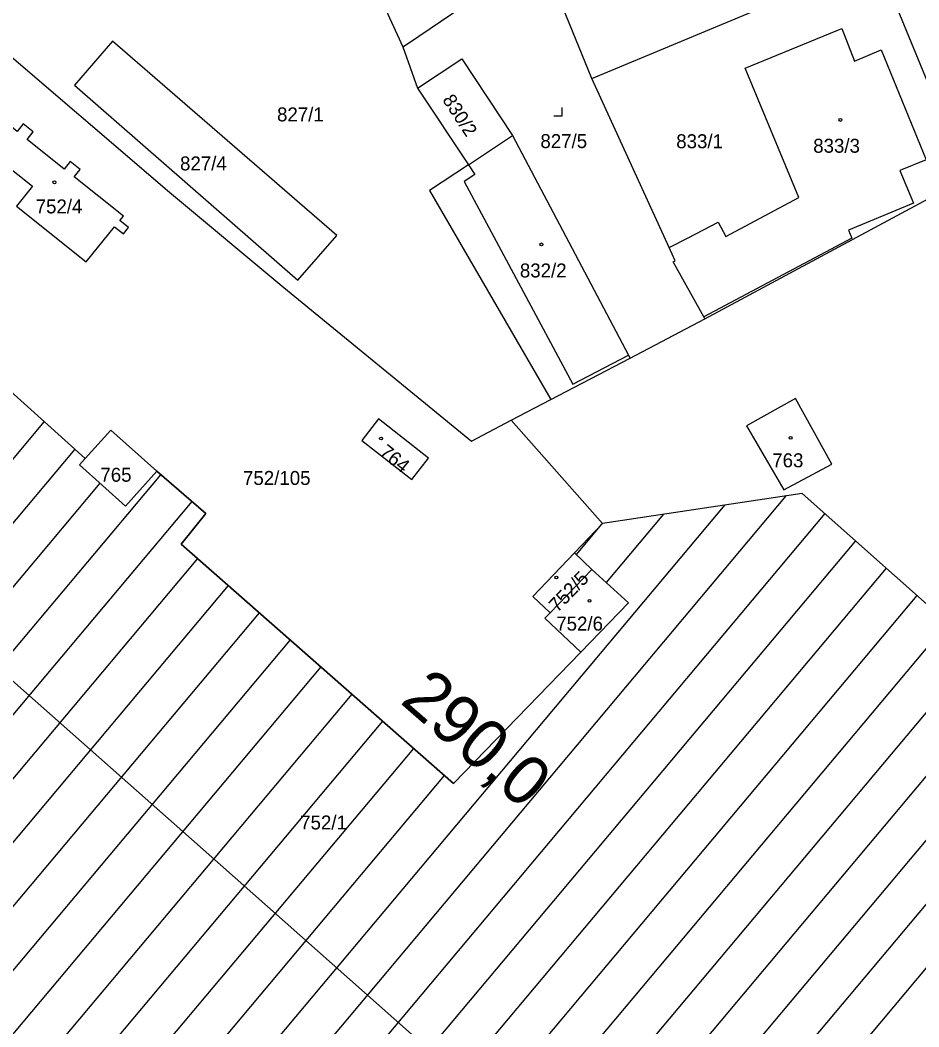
# Model space of a CAD drawing. Extents: x -496682 to -495776, y -1088797 to -1088018.
# Drawn here: x -496303.3 to -496193.9, y -1088379.3 to -1088256.7 of the extents above; entities that cross this region are included whole.
import ezdxf

# ---------------------------------------------------------------- set-up
doc = ezdxf.new("R2010")
doc.units = 0
for name, color, linetype in [('_PS01_CCTV', 7, 'Continuous'), ('Hranice parcel', 7, 'Continuous'), ('Parcelní čísla', 7, 'Continuous'), ('Vnitřní kresba', 7, 'Continuous'), ('Vrstva 20', 7, 'Continuous'), ('Vrstva 54', 7, 'Continuous'), ('Vrstva 7', 7, 'Continuous'), ('Značky budov', 7, 'Continuous'), ('Značky kultur', 7, 'Continuous')]:
    doc.layers.add(name, color=color, linetype=linetype)

msp = doc.modelspace()

# ---------------------------------------------------------------- linework, layer by layer
at = {"layer": '_PS01_CCTV'}
for p, q in [((-496278.91, -1088359.52), (-496318.03, -1088324.96)), ((-496244.22, -1088390.26), (-496278.91, -1088359.52))]:
    msp.add_line(p, q, dxfattribs=at)
at = {"layer": 'Hranice parcel'}
for p, q in [((-496188.02, -1088275.91), (-496199.66, -1088247.57)), ((-496261.03, -1088250.54), (-496256.69, -1088259.96)), ((-496256.69, -1088259.96), (-496254.9, -1088264.97)), ((-496224.27, -1088284.4), (-496233.69, -1088263.8)), ((-496254.9, -1088264.97), (-496248.71, -1088274.32)), ((-496248.71, -1088274.32), (-496243.33, -1088270.76)), ((-496219.91, -1088293.08), (-496188.02, -1088275.91)), ((-496229.03, -1088297.84), (-496219.91, -1088293.08)), ((-496219.91, -1088293.08), (-496220.05, -1088292.84)), ((-496238.7, -1088302.89), (-496229.03, -1088297.84)), ((-496243.5, -1088305.4), (-496238.7, -1088302.89)), ((-496232.37, -1088317.97), (-496243.5, -1088305.4)), ((-496232.37, -1088317.97), (-496235.81, -1088321.54)), ((-496235.81, -1088321.54), (-496233.69, -1088323.57)), ((-496238.78, -1088328.84), (-496233.69, -1088323.57))]:
    msp.add_line(p, q, dxfattribs=at)
for points in [[(-496233.69, -1088263.8), (-496239.59, -1088249.36), (-496229.63, -1088245.28)], [(-496256.69, -1088259.96), (-496256.02, -1088259.51), (-496241.58, -1088249.7)], [(-496233.69, -1088263.8), (-496212.34, -1088254.94), (-496213.15, -1088252.87)], [(-496224.27, -1088284.4), (-496221.97, -1088283.2), (-496218.31, -1088281.3), (-496217.38, -1088283.04), (-496208.49, -1088278.31), (-496215.03, -1088262.55), (-496203.26, -1088257.73), (-496201.7, -1088261.7), (-496198.45, -1088260.34), (-496192.96, -1088273.71), (-496196.19, -1088275), (-496194.54, -1088278.98), (-496202.44, -1088282.27), (-496202.01, -1088283.23), (-496220.05, -1088292.84)], [(-496306.94, -1088258.98), (-496285.12, -1088277.63), (-496271.2, -1088289.24), (-496248.36, -1088307.94), (-496243.5, -1088305.4)], [(-496292.05, -1088259.28), (-496296.7, -1088264.61), (-496269.47, -1088288.37), (-496264.72, -1088282.93), (-496292.05, -1088259.28)], [(-496254.9, -1088264.97), (-496249.52, -1088261.41), (-496243.33, -1088270.76)], [(-496295.37, -1088310.06), (-496327.63, -1088281.05), (-496324.32, -1088278.18), (-496332.44, -1088271.21), (-496325.94, -1088264.24)], [(-496303.66, -1088270.27), (-496306.43, -1088268.03), (-496305.87, -1088267.33), (-496307.07, -1088266.38), (-496307.63, -1088267.08), (-496310.05, -1088265.15), (-496312.56, -1088268.38), (-496301.78, -1088276.93), (-496303.73, -1088279.34), (-496295.25, -1088286.14), (-496291.81, -1088281.87), (-496290.73, -1088282.73), (-496290.1, -1088281.93), (-496291.18, -1088281.08), (-496290.73, -1088280.58), (-496296.73, -1088275.79), (-496296, -1088274.87), (-496297.2, -1088273.92), (-496297.93, -1088274.83), (-496302.46, -1088271.23), (-496301.72, -1088270.3), (-496302.92, -1088269.34), (-496303.66, -1088270.27)], [(-496243.33, -1088270.76), (-496229.21, -1088297.49), (-496229.03, -1088297.84)], [(-496248.71, -1088274.32), (-496253.45, -1088277.46), (-496238.7, -1088302.89)], [(-496220.05, -1088292.84), (-496223.77, -1088286.13), (-496223.53, -1088286), (-496224.27, -1088284.4)], [(-496214.86, -1088306.08), (-496210.29, -1088313.89), (-496204.48, -1088310.74), (-496208.88, -1088302.76), (-496214.86, -1088306.08)], [(-496255.61, -1088312.64), (-496253.57, -1088310.04), (-496259.65, -1088305.26), (-496261.69, -1088307.86), (-496255.61, -1088312.64)], [(-496286.66, -1088311.63), (-496292.26, -1088306.61), (-496295.37, -1088310.06)], [(-496286.66, -1088311.63), (-496290.49, -1088315.87), (-496296.07, -1088310.84), (-496295.37, -1088310.06)], [(-496235.04, -1088333.66), (-496250.52, -1088349.65), (-496283.68, -1088320.49), (-496280.68, -1088316.78), (-496286.66, -1088311.63)], [(-496085.86, -1088384.22), (-496089.4, -1088386.33), (-496106.83, -1088404.69), (-496113.8, -1088398.15), (-496126.07, -1088387.1), (-496145.34, -1088370.03), (-496208.08, -1088314.32), (-496232.37, -1088317.97)], [(-496235.81, -1088321.54), (-496240.87, -1088326.86), (-496238.78, -1088328.84)], [(-496233.69, -1088323.57), (-496229.22, -1088327.65), (-496235.04, -1088333.66)], [(-496238.78, -1088328.84), (-496239.41, -1088329.5), (-496235.04, -1088333.66)]]:
    msp.add_lwpolyline(points, dxfattribs=at)
at = {"layer": 'Vnitřní kresba'}
for p, q in [((-496248.71, -1088274.32), (-496247.93, -1088275.51)), ((-496247.93, -1088275.51), (-496249.22, -1088276.36)), ((-496249.22, -1088276.36), (-496236, -1088301.03)), ((-496236, -1088301.03), (-496229.21, -1088297.49))]:
    msp.add_line(p, q, dxfattribs=at)
at = {"layer": 'Vrstva 20'}
for p, q in [((-496343.05, -1088356.5), (-496300.33, -1088305.58)), ((-496339.65, -1088360.22), (-496296.61, -1088308.93)), ((-496329.72, -1088363.94), (-496286.16, -1088312.04)), ((-496333.65, -1088360.85), (-496293.56, -1088313.08)), ((-496325.99, -1088367.28), (-496282.37, -1088315.3)), ((-496277.96, -1088395.6), (-496209.98, -1088314.59)), ((-496282.13, -1088392.8), (-496217.45, -1088315.71)), ((-496273.15, -1088397.65), (-496205.29, -1088316.78)), ((-496231.91, -1088325.17), (-496224.91, -1088316.83)), ((-496235.57, -1088321.75), (-496232.46, -1088318.05)), ((-496269.42, -1088400.98), (-496201.55, -1088320.1)), ((-496322.27, -1088370.62), (-496281.67, -1088322.24)), ((-496265.66, -1088404.29), (-496197.81, -1088323.42)), ((-496316.25, -1088371.23), (-496277.91, -1088325.54)), ((-496261.83, -1088407.5), (-496194.07, -1088326.74)), ((-496312.54, -1088374.59), (-496274.16, -1088328.84)), ((-496257.84, -1088410.52), (-496190.33, -1088330.06)), ((-496308.83, -1088377.94), (-496270.4, -1088332.15)), ((-496253.85, -1088413.54), (-496186.59, -1088333.38)), ((-496305.04, -1088381.2), (-496266.65, -1088335.45)), ((-496249.85, -1088416.56), (-496182.85, -1088336.7)), ((-496300.46, -1088383.52), (-496262.89, -1088338.75)), ((-496245.86, -1088419.58), (-496179.11, -1088340.03)), ((-496295.88, -1088385.84), (-496259.13, -1088342.05)), ((-496241.87, -1088422.6), (-496175.37, -1088343.35)), ((-496291.3, -1088388.16), (-496255.38, -1088345.36)), ((-496237.88, -1088425.62), (-496171.63, -1088346.67)), ((-496286.72, -1088390.48), (-496251.62, -1088348.66))]:
    msp.add_line(p, q, dxfattribs=at)
at = {"layer": 'Vrstva 54'}
msp.add_lwpolyline([(-496327.63, -1088281.05), (-496295.37, -1088310.06), (-496296.07, -1088310.84), (-496290.49, -1088315.87), (-496286.66, -1088311.63), (-496280.68, -1088316.78), (-496283.68, -1088320.49), (-496250.52, -1088349.65), (-496235.04, -1088333.66)], dxfattribs=at)
at = {"layer": 'Značky budov'}
for centre in [(-496203.42, -1088268.86), (-496299.13, -1088276.45), (-496239.83, -1088284.01), (-496259.36, -1088307.63), (-496209.48, -1088307.55), (-496238, -1088324.55), (-496233.98, -1088327.4)]:
    msp.add_circle(centre, 0.175, dxfattribs=at)
at = {"layer": 'Značky kultur'}
for p, q in [((-496237.32, -1088268.36), (-496237.32, -1088267.36)), ((-496238.32, -1088268.36), (-496237.32, -1088268.36))]:
    msp.add_line(p, q, dxfattribs=at)

# ---------------------------------------------------------------- texts
at = {"layer": 'Parcelní čísla'}
for s, height, rotation, p in [('830/2', 1.65, 303, (-496251.94, -1088266.41)), ('764', 1.7, 321, (-496259.69, -1088309.54)), ('752/5', 1.7, 46, (-496237.88, -1088328.89))]:
    msp.add_text(s, height=height, rotation=rotation, dxfattribs=at).set_placement(p)
for s, p in [('827/1', (-496272.02, -1088269.03)), ('827/5', (-496239.95, -1088272.28)), ('833/1', (-496223.41, -1088272.3)), ('833/3', (-496206.73, -1088272.85)), ('827/4', (-496283.83, -1088275)), ('752/4', (-496301.41, -1088280.23)), ('832/2', (-496242.45, -1088288.03)), ('763', (-496211.72, -1088311.14)), ('765', (-496293.53, -1088312.9)), ('752/105', (-496276.16, -1088313.29)), ('752/6', (-496238.02, -1088331.02)), ('752/1', (-496269.2, -1088355.23))]:
    msp.add_text(s, height=1.7, dxfattribs=at).set_placement(p)
at = {"layer": 'Vrstva 7'}
msp.add_text('290,0', height=6, rotation=318.9438, dxfattribs=at).set_placement((-496257.17, -1088339.75))

doc.saveas('drawing.dxf')
